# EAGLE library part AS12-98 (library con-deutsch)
DEUTSCH Connector
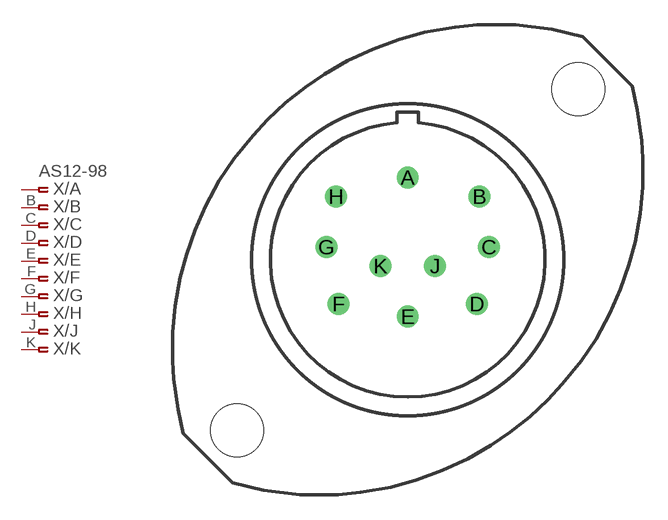
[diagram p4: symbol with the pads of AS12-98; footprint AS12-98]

Designator prefix X; gates /A=PINF_VAL /B=ASPINF /C=ASPINF /D=ASPINF /E=ASPINF /F=ASPINF /G=ASPINF /H=ASPINF /J=ASPINF /K=ASPINF

## AS12-98 (OC_FARNELL: unknown; OC_NEWARK: unknown)  [AS12-98]
A  /A:1  pas
B  /B:1  pas
C  /C:1  pas
D  /D:1  pas
E  /E:1  pas
F  /F:1  pas
G  /G:1  pas
H  /H:1  pas
J  /J:1  pas
K  /K:1  pas

## Footprint AS12-98 (pad centres in mm)
DEUTSCH Connector
drill 0.813 round: A 0,4.953; B 4.318,3.81; C 4.902,0.762; D 4.166,-2.667; E 0,-3.429; F -4.166,-2.667; G -4.902,0.762; H -4.318,3.81; J 1.651,-0.381; K -1.651,-0.381
hole 3.2 at -10.287,-10.287
hole 3.2 at 10.287,10.287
